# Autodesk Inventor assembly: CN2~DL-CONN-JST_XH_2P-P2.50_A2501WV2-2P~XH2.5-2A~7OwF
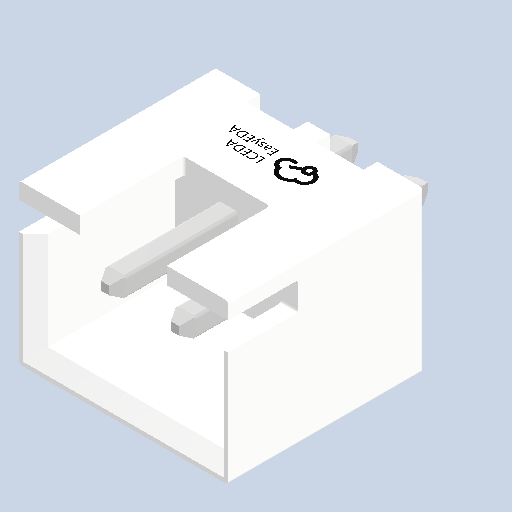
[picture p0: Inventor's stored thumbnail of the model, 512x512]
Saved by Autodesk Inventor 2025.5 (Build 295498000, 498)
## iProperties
Created: 2026-10
Part Number: CN2~DL-CONN-JST_XH_2P-P2.50_A2501WV2-2P~XH2.5-2A~7OwF
Document SubType Name: Assembly
Designer: Luis M
Author: Luis M
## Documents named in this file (2)
- C:\Users\Luis M\Downloads\3D_PCB1_2026-10-28\CN2~DL-CONN-JST_XH_2P-P2.50_A2501WV2-2P~XH2.5-2A~7OwF.iam
- C:\Users\Luis M\Downloads\3D_PCB1_2026-10-28\DL-CONN-JST_XH_2P-P2.50_A2501WV2-2P~XH2.5-2A~i7Qw.ipt
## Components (1 placed, 1 different names)
1. CN2->0
